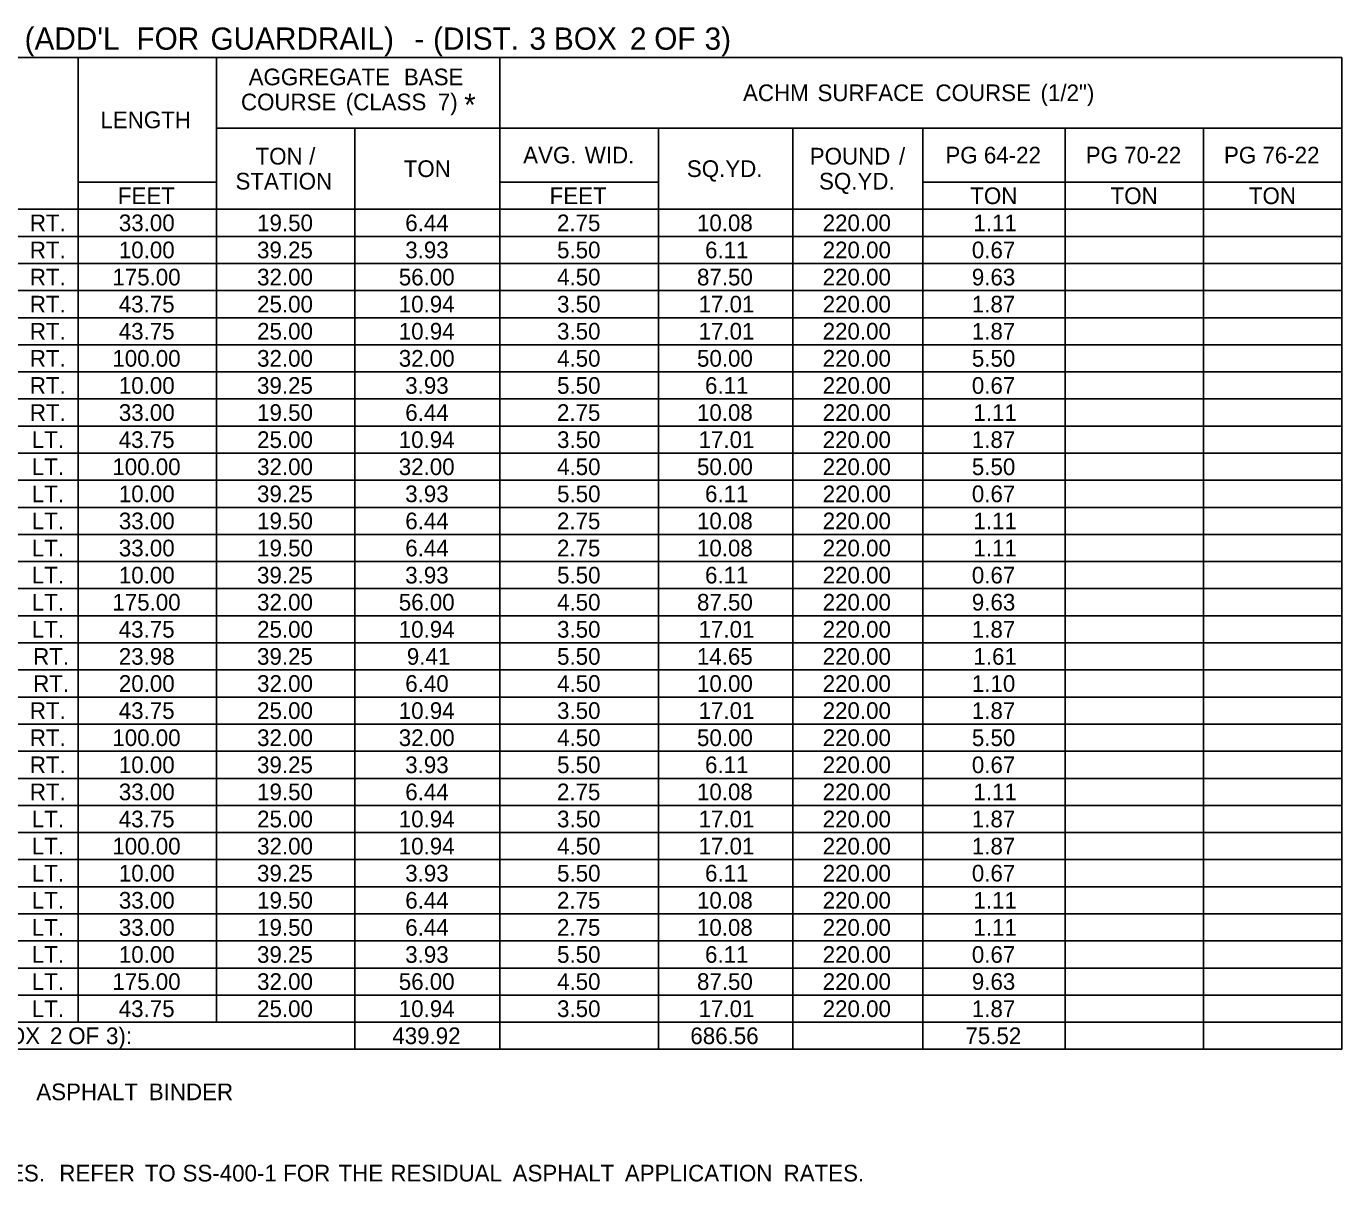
# Model space of a CAD drawing. Extents: x 544478 to 1930787, y -1948294 to 596640.
# Drawn here: x 552511.3 to 552984.3, y -1946672.6 to -1946256.9 of the extents above; entities that cross this region are included whole.
import ezdxf

# ---------------------------------------------------------------- set-up
doc = ezdxf.new("R2010")
doc.units = 0
doc.layers.add('Default', color=7, linetype='Continuous')

msp = doc.modelspace()

# ---------------------------------------------------------------- linework, layer by layer
at = {"layer": 'Default'}
for p, q in [((552161.91, -1946268.13), (552984.32, -1946268.13)), ((552161.91, -1946268.13), (552984.32, -1946268.13)), ((552529.97, -1946615.23), (552529.97, -1946268.13)), ((552579.69, -1946615.23), (552579.69, -1946268.13)), ((552681.58, -1946624.98), (552681.58, -1946268.13)), ((552984.32, -1946624.98), (552984.32, -1946268.13)), ((552579.69, -1946293.48), (552984.32, -1946293.48)), ((552629.42, -1946624.98), (552629.42, -1946293.48)), ((552738.62, -1946293.48), (552786.88, -1946293.48)), ((552738.62, -1946624.98), (552738.62, -1946293.48)), ((552786.88, -1946624.98), (552786.88, -1946293.48)), ((552833.68, -1946624.98), (552833.68, -1946293.48)), ((552884.87, -1946624.98), (552884.87, -1946293.48)), ((552934.59, -1946624.98), (552934.59, -1946293.48)), ((552529.97, -1946312.98), (552579.69, -1946312.98)), ((552579.69, -1946615.23), (552579.69, -1946312.98)), ((552681.58, -1946312.98), (552738.62, -1946312.98)), ((552681.58, -1946322.73), (552681.58, -1946312.98)), ((552738.62, -1946624.98), (552738.62, -1946312.98)), ((552833.68, -1946312.98), (552984.32, -1946312.98)), ((552161.91, -1946322.73), (552738.62, -1946322.73)), ((552529.97, -1946615.23), (552529.97, -1946322.73)), ((552579.69, -1946322.73), (552738.62, -1946322.73)), ((552629.42, -1946624.98), (552629.42, -1946322.73)), ((552738.62, -1946322.73), (552984.32, -1946322.73)), ((552786.88, -1946624.98), (552786.88, -1946322.73)), ((552407.61, -1946332.48), (552984.32, -1946332.48)), ((552407.61, -1946342.23), (552984.32, -1946342.23)), ((552407.61, -1946351.98), (552984.32, -1946351.98)), ((552407.61, -1946361.73), (552984.32, -1946361.73)), ((552407.61, -1946371.48), (552984.32, -1946371.48)), ((552407.61, -1946381.23), (552984.32, -1946381.23)), ((552407.61, -1946390.98), (552984.32, -1946390.98)), ((552407.61, -1946400.73), (552984.32, -1946400.73)), ((552407.61, -1946410.48), (552984.32, -1946410.48)), ((552407.61, -1946420.23), (552984.32, -1946420.23)), ((552407.61, -1946429.98), (552984.32, -1946429.98)), ((552407.61, -1946439.73), (552984.32, -1946439.73)), ((552407.61, -1946449.48), (552984.32, -1946449.48)), ((552407.61, -1946459.23), (552984.32, -1946459.23)), ((552407.61, -1946468.98), (552984.32, -1946468.98)), ((552161.91, -1946478.73), (552984.32, -1946478.73)), ((552786.88, -1946478.73), (552833.68, -1946478.73)), ((552407.61, -1946488.48), (552984.32, -1946488.48)), ((552407.61, -1946498.23), (552984.32, -1946498.23)), ((552407.61, -1946507.98), (552984.32, -1946507.98)), ((552407.61, -1946517.73), (552984.32, -1946517.73)), ((552407.61, -1946527.48), (552984.32, -1946527.48)), ((552407.61, -1946537.23), (552984.32, -1946537.23)), ((552407.61, -1946546.98), (552984.32, -1946546.98)), ((552407.61, -1946556.73), (552984.32, -1946556.73)), ((552407.61, -1946566.48), (552984.32, -1946566.48)), ((552407.61, -1946576.23), (552984.32, -1946576.23)), ((552407.61, -1946585.98), (552984.32, -1946585.98)), ((552407.61, -1946595.73), (552984.32, -1946595.73)), ((552407.61, -1946605.48), (552984.32, -1946605.48)), ((552161.91, -1946615.23), (552984.32, -1946615.23)), ((552833.68, -1946615.23), (552934.59, -1946615.23)), ((552833.68, -1946624.98), (552833.68, -1946615.23)), ((552934.59, -1946615.23), (552984.32, -1946615.23)), ((552407.61, -1946624.98), (552984.32, -1946624.98))]:
    msp.add_line(p, q, dxfattribs=at)

# ---------------------------------------------------------------- texts
for s, height, p in [(" (ADD'L", 8, (552507.69, -1946265.31)), (' GUARDRAIL)', 8, (552574.53, -1946265.31)), (' (DIST.', 8, (552654.59, -1946265.31)), (' 3)', 8, (552752.23, -1946265.31)), (' FOR', 8, (552547.89, -1946265.31)), (' -', 8, (552647.84, -1946265.31)), (' 3', 8, (552689.21, -1946265.31)), (' BOX', 8, (552698.05, -1946265.31)), (' 2', 8, (552725.36, -1946265.31)), (' OF', 8, (552734.12, -1946265.31)), ('AGGREGATE', 6, (552591.22, -1946278.11)), (' BASE', 6, (552644.84, -1946278.11)), ('ACHM', 6, (552769.02, -1946283.81)), (' SURFACE', 6, (552793.57, -1946283.81)), (' COURSE', 6, (552836, -1946283.81)), (' (1/2")', 6, (552873.79, -1946283.81)), ('COURSE', 6, (552588.46, -1946287.11)), (' (CLASS', 6, (552623.91, -1946287.11)), (' 7)', 6, (552657.04, -1946287.11)), ('*', 8, (552668.71, -1946289.11)), ('LENGTH', 6, (552537.92, -1946293.56)), ('TON', 6, (552593.71, -1946306.61)), (' /', 6, (552610.74, -1946306.61)), ('AVG.', 6, (552689.95, -1946306.23)), (' WID.', 6, (552709.87, -1946306.23)), ('POUND', 6, (552793.02, -1946306.61)), (' /', 6, (552822.88, -1946306.61)), ('PG', 6, (552841.8, -1946306.23)), (' 64-22', 6, (552853.41, -1946306.23)), ('PG', 6, (552892.26, -1946306.23)), (' 70-22', 6, (552903.87, -1946306.23)), ('PG', 6, (552941.98, -1946306.23)), (' 76-22', 6, (552953.59, -1946306.23)), ('TON', 6, (552646.99, -1946311.11)), ('SQ.YD.', 6, (552748.83, -1946311.11)), ('STATION', 6, (552586.49, -1946315.61)), ('SQ.YD.', 6, (552796.36, -1946315.61)), ('FEET', 6, (552544.2, -1946320.86)), ('FEET', 6, (552699.47, -1946320.86)), ('TON', 6, (552850.76, -1946320.86)), ('TON', 6, (552901.22, -1946320.86)), ('TON', 6, (552950.94, -1946320.86)), (' RT.', 6, (552510.3, -1946330.61)), ('33.00', 6, (552544.55, -1946330.61)), ('19.50', 6, (552594.27, -1946330.61)), ('6.44', 6, (552647.55, -1946330.61)), ('2.75', 6, (552702.11, -1946330.61)), ('10.08', 6, (552752.45, -1946330.61)), ('220.00', 6, (552797.67, -1946330.61)), ('1.11', 6, (552851.89, -1946330.61)), (' RT.', 6, (552510.3, -1946340.36)), ('10.00', 6, (552544.55, -1946340.36)), ('39.25', 6, (552594.24, -1946340.36)), ('3.93', 6, (552647.54, -1946340.36)), ('5.50', 6, (552702.15, -1946340.36)), ('6.11', 6, (552755.37, -1946340.36)), ('220.00', 6, (552797.67, -1946340.36)), ('0.67', 6, (552851.31, -1946340.36)), (' RT.', 6, (552510.3, -1946350.11)), ('175.00', 6, (552542.22, -1946350.11)), ('32.00', 6, (552594.27, -1946350.11)), ('56.00', 6, (552645.22, -1946350.11)), ('4.50', 6, (552702.15, -1946350.11)), ('87.50', 6, (552752.47, -1946350.11)), ('220.00', 6, (552797.67, -1946350.11)), ('9.63', 6, (552851.31, -1946350.11)), (' RT.', 6, (552510.3, -1946359.86)), ('43.75', 6, (552544.51, -1946359.86)), ('25.00', 6, (552594.27, -1946359.86)), ('10.94', 6, (552645.22, -1946359.86)), ('3.50', 6, (552702.15, -1946359.86)), ('17.01', 6, (552753.04, -1946359.86)), ('220.00', 6, (552797.67, -1946359.86)), ('1.87', 6, (552851.31, -1946359.86)), (' RT.', 6, (552510.3, -1946369.61)), ('43.75', 6, (552544.51, -1946369.61)), ('25.00', 6, (552594.27, -1946369.61)), ('10.94', 6, (552645.22, -1946369.61)), ('3.50', 6, (552702.15, -1946369.61)), ('17.01', 6, (552753.04, -1946369.61)), ('220.00', 6, (552797.67, -1946369.61)), ('1.87', 6, (552851.31, -1946369.61)), (' RT.', 6, (552510.3, -1946379.36)), ('100.00', 6, (552542.22, -1946379.36)), ('32.00', 6, (552594.27, -1946379.36)), ('32.00', 6, (552645.22, -1946379.36)), ('4.50', 6, (552702.15, -1946379.36)), ('50.00', 6, (552752.47, -1946379.36)), ('220.00', 6, (552797.67, -1946379.36)), ('5.50', 6, (552851.32, -1946379.36)), (' RT.', 6, (552510.3, -1946389.11)), ('10.00', 6, (552544.55, -1946389.11)), ('39.25', 6, (552594.24, -1946389.11)), ('3.93', 6, (552647.54, -1946389.11)), ('5.50', 6, (552702.15, -1946389.11)), ('6.11', 6, (552755.37, -1946389.11)), ('220.00', 6, (552797.67, -1946389.11)), ('0.67', 6, (552851.31, -1946389.11)), (' RT.', 6, (552510.3, -1946398.86)), ('33.00', 6, (552544.55, -1946398.86)), ('19.50', 6, (552594.27, -1946398.86)), ('6.44', 6, (552647.55, -1946398.86)), ('2.75', 6, (552702.11, -1946398.86)), ('10.08', 6, (552752.45, -1946398.86)), ('220.00', 6, (552797.67, -1946398.86)), ('1.11', 6, (552851.89, -1946398.86)), (' LT.', 6, (552511, -1946408.61)), ('43.75', 6, (552544.51, -1946408.61)), ('25.00', 6, (552594.27, -1946408.61)), ('10.94', 6, (552645.22, -1946408.61)), ('3.50', 6, (552702.15, -1946408.61)), ('17.01', 6, (552753.04, -1946408.61)), ('220.00', 6, (552797.67, -1946408.61)), ('1.87', 6, (552851.31, -1946408.61)), (' LT.', 6, (552511, -1946418.36)), ('100.00', 6, (552542.22, -1946418.36)), ('32.00', 6, (552594.27, -1946418.36)), ('32.00', 6, (552645.22, -1946418.36)), ('4.50', 6, (552702.15, -1946418.36)), ('50.00', 6, (552752.47, -1946418.36)), ('220.00', 6, (552797.67, -1946418.36)), ('5.50', 6, (552851.32, -1946418.36)), (' LT.', 6, (552511, -1946428.11)), ('10.00', 6, (552544.55, -1946428.11)), ('39.25', 6, (552594.24, -1946428.11)), ('3.93', 6, (552647.54, -1946428.11)), ('5.50', 6, (552702.15, -1946428.11)), ('6.11', 6, (552755.37, -1946428.11)), ('220.00', 6, (552797.67, -1946428.11)), ('0.67', 6, (552851.31, -1946428.11)), (' LT.', 6, (552511, -1946437.86)), ('33.00', 6, (552544.55, -1946437.86)), ('19.50', 6, (552594.27, -1946437.86)), ('6.44', 6, (552647.55, -1946437.86)), ('2.75', 6, (552702.11, -1946437.86)), ('10.08', 6, (552752.45, -1946437.86)), ('220.00', 6, (552797.67, -1946437.86)), ('1.11', 6, (552851.89, -1946437.86)), ('33.00', 6, (552544.55, -1946447.61)), ('19.50', 6, (552594.27, -1946447.61)), ('6.44', 6, (552647.55, -1946447.61)), ('2.75', 6, (552702.11, -1946447.61)), ('10.08', 6, (552752.45, -1946447.61)), ('220.00', 6, (552797.67, -1946447.61)), (' LT.', 6, (552511, -1946447.61)), ('1.11', 6, (552851.89, -1946447.61)), (' LT.', 6, (552511, -1946457.36)), ('10.00', 6, (552544.55, -1946457.36)), ('39.25', 6, (552594.24, -1946457.36)), ('3.93', 6, (552647.54, -1946457.36)), ('5.50', 6, (552702.15, -1946457.36)), ('6.11', 6, (552755.37, -1946457.36)), ('220.00', 6, (552797.67, -1946457.36)), ('0.67', 6, (552851.31, -1946457.36)), (' LT.', 6, (552511, -1946467.11)), ('175.00', 6, (552542.22, -1946467.11)), ('32.00', 6, (552594.27, -1946467.11)), ('56.00', 6, (552645.22, -1946467.11)), ('4.50', 6, (552702.15, -1946467.11)), ('87.50', 6, (552752.47, -1946467.11)), ('220.00', 6, (552797.67, -1946467.11)), ('9.63', 6, (552851.31, -1946467.11)), (' LT.', 6, (552511, -1946476.86)), ('43.75', 6, (552544.51, -1946476.86)), ('25.00', 6, (552594.27, -1946476.86)), ('10.94', 6, (552645.22, -1946476.86)), ('3.50', 6, (552702.15, -1946476.86)), ('17.01', 6, (552753.04, -1946476.86)), ('220.00', 6, (552797.67, -1946476.86)), ('1.87', 6, (552851.31, -1946476.86)), (' RT.', 6, (552511.51, -1946486.61)), ('23.98', 6, (552544.53, -1946486.61)), ('39.25', 6, (552594.24, -1946486.61)), ('9.41', 6, (552648.12, -1946486.61)), ('5.50', 6, (552702.15, -1946486.61)), ('14.65', 6, (552752.43, -1946486.61)), ('220.00', 6, (552797.67, -1946486.61)), ('1.61', 6, (552851.89, -1946486.61)), (' RT.', 6, (552511.51, -1946496.36)), ('20.00', 6, (552544.55, -1946496.36)), ('32.00', 6, (552594.27, -1946496.36)), ('6.40', 6, (552647.55, -1946496.36)), ('4.50', 6, (552702.15, -1946496.36)), ('10.00', 6, (552752.47, -1946496.36)), ('220.00', 6, (552797.67, -1946496.36)), ('1.10', 6, (552851.32, -1946496.36)), (' RT.', 6, (552510.3, -1946506.11)), ('43.75', 6, (552544.51, -1946506.11)), ('25.00', 6, (552594.27, -1946506.11)), ('10.94', 6, (552645.22, -1946506.11)), ('3.50', 6, (552702.15, -1946506.11)), ('17.01', 6, (552753.04, -1946506.11)), ('220.00', 6, (552797.67, -1946506.11)), ('1.87', 6, (552851.31, -1946506.11)), (' RT.', 6, (552510.3, -1946515.86)), ('100.00', 6, (552542.22, -1946515.86)), ('32.00', 6, (552594.27, -1946515.86)), ('32.00', 6, (552645.22, -1946515.86)), ('4.50', 6, (552702.15, -1946515.86)), ('50.00', 6, (552752.47, -1946515.86)), ('220.00', 6, (552797.67, -1946515.86)), ('5.50', 6, (552851.32, -1946515.86)), (' RT.', 6, (552510.3, -1946525.61)), ('10.00', 6, (552544.55, -1946525.61)), ('39.25', 6, (552594.24, -1946525.61)), ('3.93', 6, (552647.54, -1946525.61)), ('5.50', 6, (552702.15, -1946525.61)), ('6.11', 6, (552755.37, -1946525.61)), ('220.00', 6, (552797.67, -1946525.61)), ('0.67', 6, (552851.31, -1946525.61)), (' RT.', 6, (552510.3, -1946535.36)), ('33.00', 6, (552544.55, -1946535.36)), ('19.50', 6, (552594.27, -1946535.36)), ('6.44', 6, (552647.55, -1946535.36)), ('2.75', 6, (552702.11, -1946535.36)), ('10.08', 6, (552752.45, -1946535.36)), ('220.00', 6, (552797.67, -1946535.36)), ('1.11', 6, (552851.89, -1946535.36)), (' LT.', 6, (552511, -1946545.11)), ('43.75', 6, (552544.51, -1946545.11)), ('25.00', 6, (552594.27, -1946545.11)), ('10.94', 6, (552645.22, -1946545.11)), ('3.50', 6, (552702.15, -1946545.11)), ('17.01', 6, (552753.04, -1946545.11)), ('220.00', 6, (552797.67, -1946545.11)), ('1.87', 6, (552851.31, -1946545.11)), (' LT.', 6, (552511, -1946554.86)), ('100.00', 6, (552542.22, -1946554.86)), ('32.00', 6, (552594.27, -1946554.86)), ('10.94', 6, (552645.22, -1946554.86)), ('4.50', 6, (552702.15, -1946554.86)), ('17.01', 6, (552753.04, -1946554.86)), ('220.00', 6, (552797.67, -1946554.86)), ('1.87', 6, (552851.31, -1946554.86)), (' LT.', 6, (552511, -1946564.61)), ('10.00', 6, (552544.55, -1946564.61)), ('39.25', 6, (552594.24, -1946564.61)), ('3.93', 6, (552647.54, -1946564.61)), ('5.50', 6, (552702.15, -1946564.61)), ('6.11', 6, (552755.37, -1946564.61)), ('220.00', 6, (552797.67, -1946564.61)), ('0.67', 6, (552851.31, -1946564.61)), (' LT.', 6, (552511, -1946574.36)), ('33.00', 6, (552544.55, -1946574.36)), ('19.50', 6, (552594.27, -1946574.36)), ('6.44', 6, (552647.55, -1946574.36)), ('2.75', 6, (552702.11, -1946574.36)), ('10.08', 6, (552752.45, -1946574.36)), ('220.00', 6, (552797.67, -1946574.36)), ('1.11', 6, (552851.89, -1946574.36)), (' LT.', 6, (552511, -1946584.11)), ('33.00', 6, (552544.55, -1946584.11)), ('19.50', 6, (552594.27, -1946584.11)), ('6.44', 6, (552647.55, -1946584.11)), ('2.75', 6, (552702.11, -1946584.11)), ('10.08', 6, (552752.45, -1946584.11)), ('220.00', 6, (552797.67, -1946584.11)), ('1.11', 6, (552851.89, -1946584.11)), (' LT.', 6, (552511, -1946593.86)), ('10.00', 6, (552544.55, -1946593.86)), ('39.25', 6, (552594.24, -1946593.86)), ('3.93', 6, (552647.54, -1946593.86)), ('5.50', 6, (552702.15, -1946593.86)), ('6.11', 6, (552755.37, -1946593.86)), ('220.00', 6, (552797.67, -1946593.86)), ('0.67', 6, (552851.31, -1946593.86)), (' LT.', 6, (552511, -1946603.61)), ('175.00', 6, (552542.22, -1946603.61)), ('32.00', 6, (552594.27, -1946603.61)), ('56.00', 6, (552645.22, -1946603.61)), ('4.50', 6, (552702.15, -1946603.61)), ('87.50', 6, (552752.47, -1946603.61)), ('220.00', 6, (552797.67, -1946603.61)), ('9.63', 6, (552851.31, -1946603.61)), (' LT.', 6, (552511, -1946613.36)), ('43.75', 6, (552544.51, -1946613.36)), ('25.00', 6, (552594.27, -1946613.36)), ('10.94', 6, (552645.22, -1946613.36)), ('3.50', 6, (552702.15, -1946613.36)), ('17.01', 6, (552753.04, -1946613.36)), ('220.00', 6, (552797.67, -1946613.36)), ('1.87', 6, (552851.31, -1946613.36)), (' BOX', 6, (552497.06, -1946623.11)), (' 2', 6, (552517.55, -1946623.11)), (' OF', 6, (552524.11, -1946623.11)), (' 3):', 6, (552537.7, -1946623.11)), ('439.92', 6, (552642.9, -1946623.11)), ('686.56', 6, (552750.08, -1946623.11)), ('75.52', 6, (552849, -1946623.11)), ('  ASPHALT', 6, (552510.4, -1946643.28)), (' BINDER', 6, (552553.09, -1946643.28)), (' RATES.', 6, (552486.78, -1946672.53)), ('  REFER', 6, (552518.66, -1946672.53)), (' TO', 6, (552551.62, -1946672.53)), (' SS-400-1', 6, (552565.22, -1946672.53)), (' FOR', 6, (552601.41, -1946672.53)), (' THE', 6, (552621.32, -1946672.53)), (' RESIDUAL', 6, (552639.97, -1946672.53)), (' ASPHALT', 6, (552683.93, -1946672.53)), (' APPLICATION', 6, (552724.3, -1946672.53)), (' RATES.', 6, (552781.38, -1946672.53))]:
    msp.add_text(s, height=height, dxfattribs=at).set_placement(p)

doc.saveas('drawing.dxf')
